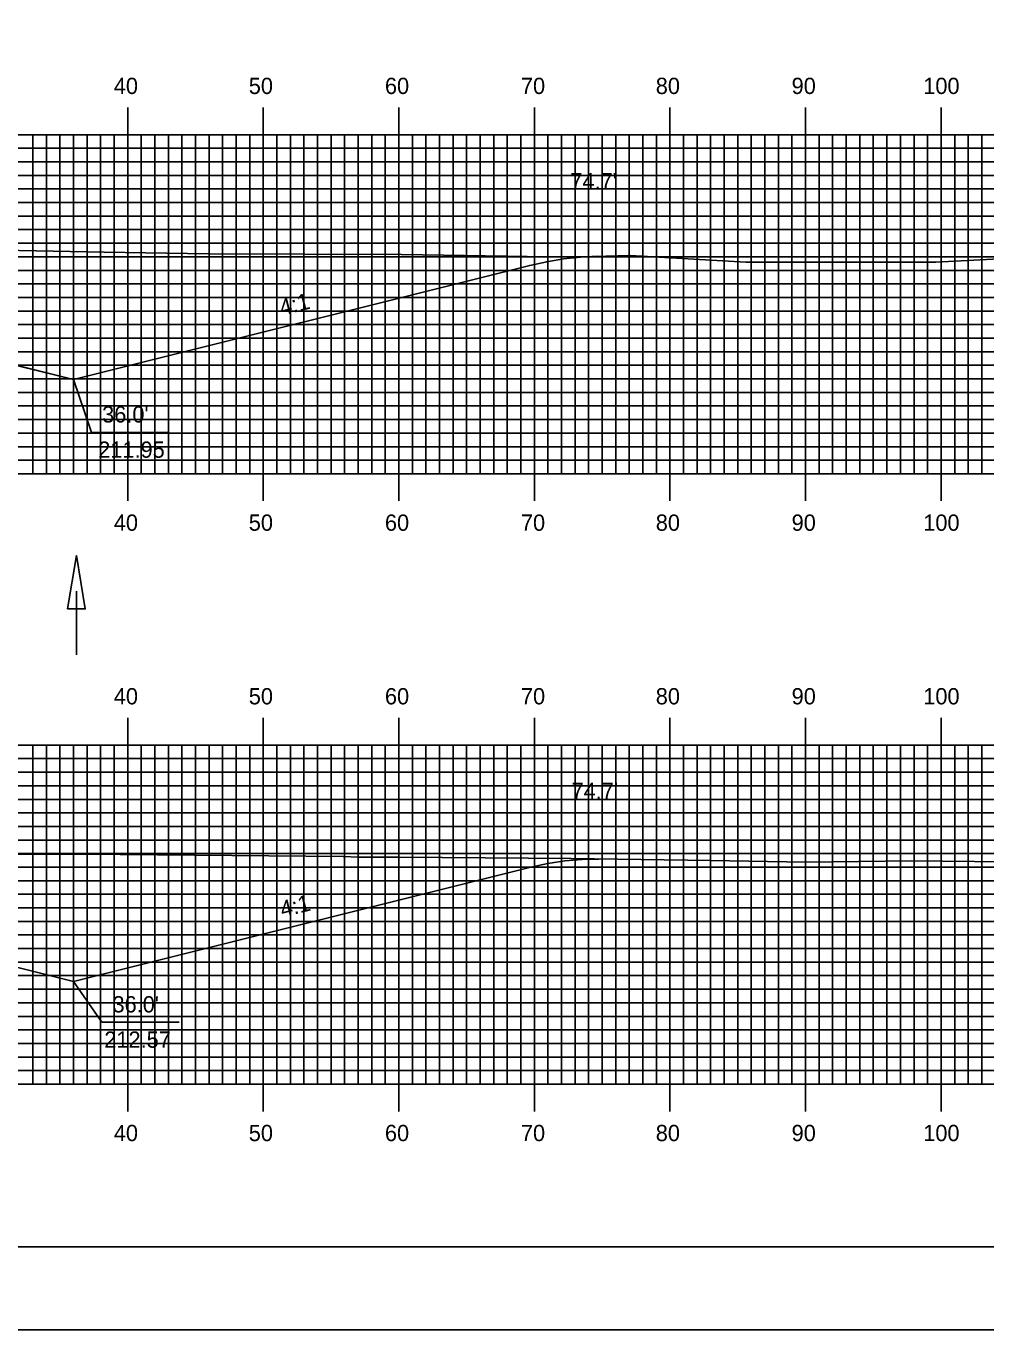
# Model space of a CAD drawing. Extents: x 1820818 to 1821161, y 442591 to 442811.
# Drawn here: x 1821016.2 to 1821087, y 442590.5 to 442686.7 of the extents above; entities that cross this region are included whole.
import ezdxf

# ---------------------------------------------------------------- set-up
doc = ezdxf.new("R2010")
doc.units = 0
for name, color, linetype in [('ANNOTATION', 7, 'Continuous'), ('BORDER', 7, 'Continuous'), ('D_Drainage_Ditch_Line', 7, 'Continuous'), ('D_Roadway_Centerline', 7, 'Continuous'), ('D_Roadway_SlopeLines', 7, 'Continuous'), ('D_Text_Standard', 7, 'Continuous'), ('H_V ANNOTATION', 7, 'Continuous'), ('MAJOR', 7, 'Continuous'), ('MINOR', 7, 'Continuous'), ('PLOT BOUNDARY', 7, 'Continuous'), ('S_Roadway_Centerline', 7, 'Continuous')]:
    doc.layers.add(name, color=color, linetype=linetype)

msp = doc.modelspace()

# ---------------------------------------------------------------- linework, layer by layer
at = {"layer": 'ANNOTATION'}
for points in [[(1821026.743, 442656.721), (1821021.052, 442656.721), (1821019.717, 442660.612)], [(1821027.508, 442613.226), (1821021.816, 442613.226), (1821019.717, 442616.237)]]:
    msp.add_lwpolyline(points, dxfattribs=at)
at = {"layer": 'BORDER'}
msp.add_lwpolyline([(1820834.117, 442596.665), (1821154.117, 442596.665), (1821154.117, 442806.665), (1820834.117, 442806.665)], close=True, dxfattribs=at)
at = {"layer": 'D_Drainage_Ditch_Line'}
msp.add_line((1821019.926, 442645.015), (1821019.927, 442640.316), dxfattribs=at)
msp.add_lwpolyline([(1821019.27, 442643.702), (1821020.582, 442643.702), (1821019.926, 442647.639)], close=True, dxfattribs=at)
at = {"layer": 'D_Roadway_Centerline'}
for points in [[(1820902.223, 442671.823), (1820903.473, 442671.797), (1820904.723, 442671.689), (1820905.973, 442671.5), (1820907.223, 442671.228), (1820949.543, 442660.648), (1820953.543, 442661.648), (1820963.717, 442664.192), (1820971.717, 442664.512), (1820983.717, 442664.752), (1820995.717, 442664.512), (1821005.717, 442664.112), (1821015.717, 442661.612), (1821019.717, 442660.612), (1821053.372, 442669.025), (1821054.622, 442669.302), (1821055.872, 442669.507), (1821057.122, 442669.64), (1821058.372, 442669.702)], [(1820903.857, 442627.07), (1820905.107, 442627.031), (1820906.357, 442626.913), (1820907.607, 442626.718), (1820908.857, 442626.445), (1820949.543, 442616.273), (1820953.543, 442617.273), (1820963.717, 442619.817), (1820971.717, 442620.137), (1820983.717, 442620.377), (1820995.717, 442620.137), (1821005.717, 442619.737), (1821015.717, 442617.237), (1821019.717, 442616.237), (1821053.462, 442624.673), (1821054.712, 442624.944), (1821055.962, 442625.133), (1821057.212, 442625.24), (1821058.462, 442625.265)]]:
    msp.add_lwpolyline(points, dxfattribs=at)
at = {"layer": 'D_Roadway_SlopeLines'}
for points in [[(1821019.717, 442660.612), (1821053.372, 442669.025), (1821054.622, 442669.302), (1821055.872, 442669.507), (1821057.122, 442669.64), (1821058.372, 442669.702)], [(1821005.717, 442664.112), (1821019.717, 442660.612)], [(1821019.717, 442616.237), (1821053.462, 442624.673), (1821054.712, 442624.944), (1821055.962, 442625.133), (1821057.212, 442625.24), (1821058.462, 442625.265)], [(1821005.717, 442619.737), (1821019.717, 442616.237)]]:
    msp.add_lwpolyline(points, dxfattribs=at)
at = {"layer": 'MAJOR'}
for p, q in [((1821023.717, 442680.669), (1821023.717, 442678.665)), ((1821033.717, 442680.669), (1821033.717, 442678.665)), ((1821043.717, 442680.669), (1821043.717, 442678.665)), ((1821053.717, 442680.669), (1821053.717, 442678.665)), ((1821063.717, 442680.669), (1821063.717, 442678.665)), ((1821073.717, 442680.669), (1821073.717, 442678.665)), ((1821083.717, 442680.669), (1821083.717, 442678.665)), ((1820843.717, 442678.665), (1821123.717, 442678.665)), ((1820843.717, 442678.665), (1821123.717, 442678.665)), ((1821023.717, 442653.665), (1821023.717, 442678.665)), ((1821033.717, 442653.665), (1821033.717, 442678.665)), ((1821043.717, 442653.665), (1821043.717, 442678.665)), ((1821053.717, 442653.665), (1821053.717, 442678.665)), ((1821063.717, 442653.665), (1821063.717, 442678.665)), ((1821073.717, 442653.665), (1821073.717, 442678.665)), ((1821083.717, 442653.665), (1821083.717, 442678.665)), ((1820843.717, 442673.665), (1821123.717, 442673.665)), ((1820843.717, 442668.665), (1821123.717, 442668.665)), ((1820843.717, 442663.665), (1821123.717, 442663.665)), ((1820843.717, 442658.665), (1821123.717, 442658.665)), ((1820843.717, 442653.665), (1821123.717, 442653.665)), ((1820843.717, 442653.665), (1821123.717, 442653.665)), ((1821023.717, 442651.661), (1821023.717, 442653.665)), ((1821033.717, 442651.661), (1821033.717, 442653.665)), ((1821043.717, 442651.661), (1821043.717, 442653.665)), ((1821053.717, 442651.661), (1821053.717, 442653.665)), ((1821063.717, 442651.661), (1821063.717, 442653.665)), ((1821073.717, 442651.661), (1821073.717, 442653.665)), ((1821083.717, 442651.661), (1821083.717, 442653.665)), ((1821023.717, 442635.669), (1821023.717, 442633.665)), ((1821033.717, 442635.669), (1821033.717, 442633.665)), ((1821043.717, 442635.669), (1821043.717, 442633.665)), ((1821053.717, 442635.669), (1821053.717, 442633.665)), ((1821063.717, 442635.669), (1821063.717, 442633.665)), ((1821073.717, 442635.669), (1821073.717, 442633.665)), ((1821083.717, 442635.669), (1821083.717, 442633.665)), ((1820843.717, 442633.665), (1821123.717, 442633.665)), ((1820843.717, 442633.665), (1821123.717, 442633.665)), ((1821023.717, 442608.665), (1821023.717, 442633.665)), ((1821033.717, 442608.665), (1821033.717, 442633.665)), ((1821043.717, 442608.665), (1821043.717, 442633.665)), ((1821053.717, 442608.665), (1821053.717, 442633.665)), ((1821063.717, 442608.665), (1821063.717, 442633.665)), ((1821073.717, 442608.665), (1821073.717, 442633.665)), ((1821083.717, 442608.665), (1821083.717, 442633.665)), ((1820843.717, 442628.665), (1821123.717, 442628.665)), ((1820843.717, 442623.665), (1821123.717, 442623.665)), ((1820843.717, 442618.665), (1821123.717, 442618.665)), ((1820843.717, 442613.665), (1821123.717, 442613.665)), ((1820843.717, 442608.665), (1821123.717, 442608.665)), ((1820843.717, 442608.665), (1821123.717, 442608.665)), ((1821023.717, 442606.661), (1821023.717, 442608.665)), ((1821033.717, 442606.661), (1821033.717, 442608.665)), ((1821043.717, 442606.661), (1821043.717, 442608.665)), ((1821053.717, 442606.661), (1821053.717, 442608.665)), ((1821063.717, 442606.661), (1821063.717, 442608.665)), ((1821073.717, 442606.661), (1821073.717, 442608.665)), ((1821083.717, 442606.661), (1821083.717, 442608.665))]:
    msp.add_line(p, q, dxfattribs=at)
at = {"layer": 'MINOR'}
for p, q in [((1821016.717, 442653.665), (1821016.717, 442678.665)), ((1821017.717, 442653.665), (1821017.717, 442678.665)), ((1821018.717, 442653.665), (1821018.717, 442678.665)), ((1821019.717, 442653.665), (1821019.717, 442678.665)), ((1821020.717, 442653.665), (1821020.717, 442678.665)), ((1821021.717, 442653.665), (1821021.717, 442678.665)), ((1821022.717, 442653.665), (1821022.717, 442678.665)), ((1821024.717, 442653.665), (1821024.717, 442678.665)), ((1821025.717, 442653.665), (1821025.717, 442678.665)), ((1821026.717, 442653.665), (1821026.717, 442678.665)), ((1821027.717, 442653.665), (1821027.717, 442678.665)), ((1821028.717, 442653.665), (1821028.717, 442678.665)), ((1821029.717, 442653.665), (1821029.717, 442678.665)), ((1821030.717, 442653.665), (1821030.717, 442678.665)), ((1821031.717, 442653.665), (1821031.717, 442678.665)), ((1821032.717, 442653.665), (1821032.717, 442678.665)), ((1821034.717, 442653.665), (1821034.717, 442678.665)), ((1821035.717, 442653.665), (1821035.717, 442678.665)), ((1821036.717, 442653.665), (1821036.717, 442678.665)), ((1821037.717, 442653.665), (1821037.717, 442678.665)), ((1821038.717, 442653.665), (1821038.717, 442678.665)), ((1821039.717, 442653.665), (1821039.717, 442678.665)), ((1821040.717, 442653.665), (1821040.717, 442678.665)), ((1821041.717, 442653.665), (1821041.717, 442678.665)), ((1821042.717, 442653.665), (1821042.717, 442678.665)), ((1821044.717, 442653.665), (1821044.717, 442678.665)), ((1821045.717, 442653.665), (1821045.717, 442678.665)), ((1821046.717, 442653.665), (1821046.717, 442678.665)), ((1821047.717, 442653.665), (1821047.717, 442678.665)), ((1821048.717, 442653.665), (1821048.717, 442678.665)), ((1821049.717, 442653.665), (1821049.717, 442678.665)), ((1821050.717, 442653.665), (1821050.717, 442678.665)), ((1821051.717, 442653.665), (1821051.717, 442678.665)), ((1821052.717, 442653.665), (1821052.717, 442678.665)), ((1821054.717, 442653.665), (1821054.717, 442678.665)), ((1821055.717, 442653.665), (1821055.717, 442678.665)), ((1821056.717, 442653.665), (1821056.717, 442678.665)), ((1821057.717, 442653.665), (1821057.717, 442678.665)), ((1821058.717, 442653.665), (1821058.717, 442678.665)), ((1821059.717, 442653.665), (1821059.717, 442678.665)), ((1821060.717, 442653.665), (1821060.717, 442678.665)), ((1821061.717, 442653.665), (1821061.717, 442678.665)), ((1821062.717, 442653.665), (1821062.717, 442678.665)), ((1821064.717, 442653.665), (1821064.717, 442678.665)), ((1821065.717, 442653.665), (1821065.717, 442678.665)), ((1821066.717, 442653.665), (1821066.717, 442678.665)), ((1821067.717, 442653.665), (1821067.717, 442678.665)), ((1821068.717, 442653.665), (1821068.717, 442678.665)), ((1821069.717, 442653.665), (1821069.717, 442678.665)), ((1821070.717, 442653.665), (1821070.717, 442678.665)), ((1821071.717, 442653.665), (1821071.717, 442678.665)), ((1821072.717, 442653.665), (1821072.717, 442678.665)), ((1821074.717, 442653.665), (1821074.717, 442678.665)), ((1821075.717, 442653.665), (1821075.717, 442678.665)), ((1821076.717, 442653.665), (1821076.717, 442678.665)), ((1821077.717, 442653.665), (1821077.717, 442678.665)), ((1821078.717, 442653.665), (1821078.717, 442678.665)), ((1821079.717, 442653.665), (1821079.717, 442678.665)), ((1821080.717, 442653.665), (1821080.717, 442678.665)), ((1821081.717, 442653.665), (1821081.717, 442678.665)), ((1821082.717, 442653.665), (1821082.717, 442678.665)), ((1821084.717, 442653.665), (1821084.717, 442678.665)), ((1821085.717, 442653.665), (1821085.717, 442678.665)), ((1821086.717, 442653.665), (1821086.717, 442678.665)), ((1820843.717, 442677.665), (1821123.717, 442677.665)), ((1820843.717, 442676.665), (1821123.717, 442676.665)), ((1820843.717, 442675.665), (1821123.717, 442675.665)), ((1820843.717, 442674.665), (1821123.717, 442674.665)), ((1820843.717, 442672.665), (1821123.717, 442672.665)), ((1820843.717, 442671.665), (1821123.717, 442671.665)), ((1820843.717, 442670.665), (1821123.717, 442670.665)), ((1820843.717, 442669.665), (1821123.717, 442669.665)), ((1820843.717, 442667.665), (1821123.717, 442667.665)), ((1820843.717, 442666.665), (1821123.717, 442666.665)), ((1820843.717, 442665.665), (1821123.717, 442665.665)), ((1820843.717, 442664.665), (1821123.717, 442664.665)), ((1820843.717, 442662.665), (1821123.717, 442662.665)), ((1820843.717, 442661.665), (1821123.717, 442661.665)), ((1820843.717, 442660.665), (1821123.717, 442660.665)), ((1820843.717, 442659.665), (1821123.717, 442659.665)), ((1820843.717, 442657.665), (1821123.717, 442657.665)), ((1820843.717, 442656.665), (1821123.717, 442656.665)), ((1820843.717, 442655.665), (1821123.717, 442655.665)), ((1820843.717, 442654.665), (1821123.717, 442654.665)), ((1821016.717, 442608.665), (1821016.717, 442633.665)), ((1821017.717, 442608.665), (1821017.717, 442633.665)), ((1821018.717, 442608.665), (1821018.717, 442633.665)), ((1821019.717, 442608.665), (1821019.717, 442633.665)), ((1821020.717, 442608.665), (1821020.717, 442633.665)), ((1821021.717, 442608.665), (1821021.717, 442633.665)), ((1821022.717, 442608.665), (1821022.717, 442633.665)), ((1821024.717, 442608.665), (1821024.717, 442633.665)), ((1821025.717, 442608.665), (1821025.717, 442633.665)), ((1821026.717, 442608.665), (1821026.717, 442633.665)), ((1821027.717, 442608.665), (1821027.717, 442633.665)), ((1821028.717, 442608.665), (1821028.717, 442633.665)), ((1821029.717, 442608.665), (1821029.717, 442633.665)), ((1821030.717, 442608.665), (1821030.717, 442633.665)), ((1821031.717, 442608.665), (1821031.717, 442633.665)), ((1821032.717, 442608.665), (1821032.717, 442633.665)), ((1821034.717, 442608.665), (1821034.717, 442633.665)), ((1821035.717, 442608.665), (1821035.717, 442633.665)), ((1821036.717, 442608.665), (1821036.717, 442633.665)), ((1821037.717, 442608.665), (1821037.717, 442633.665)), ((1821038.717, 442608.665), (1821038.717, 442633.665)), ((1821039.717, 442608.665), (1821039.717, 442633.665)), ((1821040.717, 442608.665), (1821040.717, 442633.665)), ((1821041.717, 442608.665), (1821041.717, 442633.665)), ((1821042.717, 442608.665), (1821042.717, 442633.665)), ((1821044.717, 442608.665), (1821044.717, 442633.665)), ((1821045.717, 442608.665), (1821045.717, 442633.665)), ((1821046.717, 442608.665), (1821046.717, 442633.665)), ((1821047.717, 442608.665), (1821047.717, 442633.665)), ((1821048.717, 442608.665), (1821048.717, 442633.665)), ((1821049.717, 442608.665), (1821049.717, 442633.665)), ((1821050.717, 442608.665), (1821050.717, 442633.665)), ((1821051.717, 442608.665), (1821051.717, 442633.665)), ((1821052.717, 442608.665), (1821052.717, 442633.665)), ((1821054.717, 442608.665), (1821054.717, 442633.665)), ((1821055.717, 442608.665), (1821055.717, 442633.665)), ((1821056.717, 442608.665), (1821056.717, 442633.665)), ((1821057.717, 442608.665), (1821057.717, 442633.665)), ((1821058.717, 442608.665), (1821058.717, 442633.665)), ((1821059.717, 442608.665), (1821059.717, 442633.665)), ((1821060.717, 442608.665), (1821060.717, 442633.665)), ((1821061.717, 442608.665), (1821061.717, 442633.665)), ((1821062.717, 442608.665), (1821062.717, 442633.665)), ((1821064.717, 442608.665), (1821064.717, 442633.665)), ((1821065.717, 442608.665), (1821065.717, 442633.665)), ((1821066.717, 442608.665), (1821066.717, 442633.665)), ((1821067.717, 442608.665), (1821067.717, 442633.665)), ((1821068.717, 442608.665), (1821068.717, 442633.665)), ((1821069.717, 442608.665), (1821069.717, 442633.665)), ((1821070.717, 442608.665), (1821070.717, 442633.665)), ((1821071.717, 442608.665), (1821071.717, 442633.665)), ((1821072.717, 442608.665), (1821072.717, 442633.665)), ((1821074.717, 442608.665), (1821074.717, 442633.665)), ((1821075.717, 442608.665), (1821075.717, 442633.665)), ((1821076.717, 442608.665), (1821076.717, 442633.665)), ((1821077.717, 442608.665), (1821077.717, 442633.665)), ((1821078.717, 442608.665), (1821078.717, 442633.665)), ((1821079.717, 442608.665), (1821079.717, 442633.665)), ((1821080.717, 442608.665), (1821080.717, 442633.665)), ((1821081.717, 442608.665), (1821081.717, 442633.665)), ((1821082.717, 442608.665), (1821082.717, 442633.665)), ((1821084.717, 442608.665), (1821084.717, 442633.665)), ((1821085.717, 442608.665), (1821085.717, 442633.665)), ((1821086.717, 442608.665), (1821086.717, 442633.665)), ((1820843.717, 442632.665), (1821123.717, 442632.665)), ((1820843.717, 442631.665), (1821123.717, 442631.665)), ((1820843.717, 442630.665), (1821123.717, 442630.665)), ((1820843.717, 442629.665), (1821123.717, 442629.665)), ((1820843.717, 442627.665), (1821123.717, 442627.665)), ((1820843.717, 442626.665), (1821123.717, 442626.665)), ((1820843.717, 442625.665), (1821123.717, 442625.665)), ((1820843.717, 442624.665), (1821123.717, 442624.665)), ((1820843.717, 442622.665), (1821123.717, 442622.665)), ((1820843.717, 442621.665), (1821123.717, 442621.665)), ((1820843.717, 442620.665), (1821123.717, 442620.665)), ((1820843.717, 442619.665), (1821123.717, 442619.665)), ((1820843.717, 442617.665), (1821123.717, 442617.665)), ((1820843.717, 442616.665), (1821123.717, 442616.665)), ((1820843.717, 442615.665), (1821123.717, 442615.665)), ((1820843.717, 442614.665), (1821123.717, 442614.665)), ((1820843.717, 442612.665), (1821123.717, 442612.665)), ((1820843.717, 442611.665), (1821123.717, 442611.665)), ((1820843.717, 442610.665), (1821123.717, 442610.665)), ((1820843.717, 442609.665), (1821123.717, 442609.665))]:
    msp.add_line(p, q, dxfattribs=at)
at = {"layer": 'PLOT BOUNDARY'}
msp.add_lwpolyline([(1820817.93, 442590.547), (1821157.93, 442590.547), (1821157.93, 442810.547), (1820817.93, 442810.547)], close=True, dxfattribs=at)
at = {"layer": 'S_Roadway_Centerline'}
for points in [[(1821009.437, 442670.252), (1821021.978, 442670.008), (1821029.676, 442669.872), (1821043.901, 442669.845), (1821056.274, 442669.644), (1821060.771, 442669.769), (1821069.309, 442669.278), (1821077.78, 442669.268), (1821083.32, 442669.276), (1821094.051, 442669.83), (1821103.872, 442669.929), (1821111.66, 442670.028), (1821113.217, 442670.079), (1821123.717, 442670.297)], [(1821014.126, 442625.623), (1821023.163, 442625.591), (1821039.611, 442625.441), (1821040.758, 442625.408), (1821041.415, 442625.407), (1821043.729, 442625.399), (1821056.429, 442625.294), (1821066.724, 442625.147), (1821073.701, 442625.024), (1821081.532, 442625.143), (1821090.793, 442625.035), (1821106.787, 442624.768), (1821107.541, 442624.739), (1821107.967, 442624.753), (1821109.525, 442624.738), (1821120.883, 442624.627), (1821123.717, 442624.667)]]:
    msp.add_lwpolyline(points, dxfattribs=at)

# ---------------------------------------------------------------- texts
at = {"layer": 'ANNOTATION'}
for p in [(1821035.08, 442665.314), (1821035.125, 442620.95)]:
    msp.add_text('4:1', height=1.2, rotation=14.03624, dxfattribs=at).set_placement(p)
for s, p in [("36.0'", (1821021.829, 442657.447)), ('211.95', (1821021.54, 442654.847)), ("36.0'", (1821022.593, 442613.953)), ('212.57', (1821021.988, 442611.353))]:
    msp.add_text(s, height=1.2, dxfattribs=at).set_placement(p)
at = {"layer": 'D_Text_Standard'}
for p in [(1821056.366, 442674.636), (1821056.455, 442629.682)]:
    msp.add_text("74.7'", height=1.2, dxfattribs=at).set_placement(p)
at = {"layer": 'H_V ANNOTATION'}
for s, p in [('40', (1821022.689, 442681.665)), ('50', (1821032.646, 442681.665)), ('60', (1821042.689, 442681.665)), ('70', (1821052.721, 442681.665)), ('80', (1821062.668, 442681.665)), ('90', (1821072.689, 442681.665)), ('100', (1821082.4, 442681.665)), ('40', (1821022.689, 442649.465)), ('50', (1821032.646, 442649.465)), ('60', (1821042.689, 442649.465)), ('70', (1821052.721, 442649.465)), ('80', (1821062.668, 442649.465)), ('90', (1821072.689, 442649.465)), ('100', (1821082.4, 442649.465)), ('40', (1821022.689, 442636.665)), ('50', (1821032.646, 442636.665)), ('60', (1821042.689, 442636.665)), ('70', (1821052.721, 442636.665)), ('80', (1821062.668, 442636.665)), ('90', (1821072.689, 442636.665)), ('100', (1821082.4, 442636.665)), ('40', (1821022.689, 442604.465)), ('50', (1821032.646, 442604.465)), ('60', (1821042.689, 442604.465)), ('70', (1821052.721, 442604.465)), ('80', (1821062.668, 442604.465)), ('90', (1821072.689, 442604.465)), ('100', (1821082.4, 442604.465))]:
    msp.add_text(s, height=1.2, dxfattribs=at).set_placement(p)

doc.saveas('drawing.dxf')
